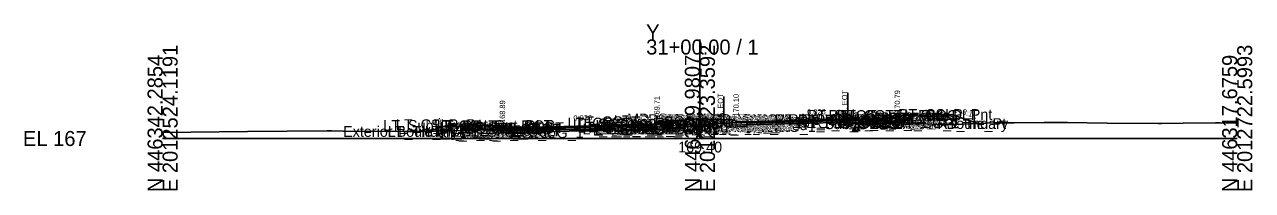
# Model space of a CAD drawing. Extents: x -26 to 3203, y -10 to 9532.
# Drawn here: x 1974.3 to 2202.8, y 4990.3 to 5021.3 of the extents above; entities that cross this region are included whole.
import ezdxf

# ---------------------------------------------------------------- set-up
doc = ezdxf.new("R2010")
doc.units = 0
for name, color, linetype in [('Default', 7, 'Continuous'), ('Exist CMT Pavement', 7, 'Continuous'), ('Exist Cross Section Cell', 7, 'Continuous'), ('Exist XS Center Line Elevation Label', 7, 'Continuous'), ('Exist XS Ground Line', 7, 'Continuous'), ('Prop CMT Conc Surface', 7, 'Continuous'), ('Prop CMT Concrete Structures', 7, 'Continuous'), ('Prop CMT Pvmt Course 1', 7, 'Continuous'), ('Prop CMT Pvmt Course 1 CG', 7, 'Continuous'), ('Prop CMT Pvmt Course 2', 7, 'Continuous'), ('Prop CMT Pvmt Course 3', 7, 'Continuous'), ('Prop CMT Pvmt Surface', 7, 'Continuous'), ('Prop CMT Pvmt Wedge Surface 2', 7, 'Continuous'), ('Prop CMT Pvmt Wedge Surface 3', 7, 'Continuous'), ('Prop CMT Slope Grass', 7, 'Continuous'), ('Prop CMT Subgrade Earthwork', 7, 'Continuous'), ('Prop XS Hydro Elevations', 7, 'Continuous'), ('Prop XS Label Text', 7, 'Continuous'), ('Prop XS SE Text', 7, 'Continuous'), ('Prop XS Side Slope Text', 7, 'Continuous'), ('Scratch_Level_0', 7, 'Continuous')]:
    doc.layers.add(name, color=color, linetype=linetype)

msp = doc.modelspace()

# ---------------------------------------------------------------- linework, layer by layer
at = {"layer": 'Exist CMT Pavement'}
msp.add_lwpolyline([(2104.43, 5002.86), (2104.43, 5002.86), (2105.54, 5002.89), (2106.21, 5002.91), (2107.69, 5002.97), (2108.73, 5003.02), (2109.96, 5003.05), (2111.26, 5003.09), (2112.93, 5003.13), (2113.77, 5003.16), (2115.18, 5003.2), (2115.89, 5003.22), (2116.19, 5003.23), (2118.43, 5003.29), (2118.78, 5003.3), (2119.68, 5003.33), (2121.53, 5003.38), (2123.82, 5003.42), (2125.6, 5003.46), (2126.34, 5003.48), (2126.99, 5003.49), (2127.53, 5003.51)], dxfattribs=at)
at = {"layer": 'Exist Cross Section Cell'}
for p, q in [((2100, 5000), (2100, 5018.46)), ((2000, 5000), (2100, 5000)), ((2100, 5000), (2200, 5000))]:
    msp.add_line(p, q, dxfattribs=at)
at = {"layer": 'Exist XS Ground Line'}
msp.add_lwpolyline([(2000, 5001.15), (2015.79, 5001.29), (2030.64, 5001.42), (2031.45, 5001.41), (2033.69, 5001.39), (2045.17, 5001.28), (2048.27, 5001.28), (2060.81, 5001.6), (2064.95, 5001.67), (2070.94, 5001.68), (2082.26, 5001.66), (2087.67, 5001.5), (2088.16, 5001.47), (2089.88, 5001.58), (2095.46, 5001.91), (2100.26, 5002.43), (2103.24, 5002.77), (2104.01, 5002.84), (2104.43, 5002.86), (2105.54, 5002.89), (2106.21, 5002.91), (2107.69, 5002.97), (2108.73, 5003.02), (2109.96, 5003.05), (2111.26, 5003.09), (2112.93, 5003.13), (2113.77, 5003.16), (2115.18, 5003.2), (2115.89, 5003.22), (2116.19, 5003.23), (2118.43, 5003.29), (2118.78, 5003.3), (2119.68, 5003.33), (2121.53, 5003.38), (2123.82, 5003.42), (2125.6, 5003.46), (2126.34, 5003.48), (2126.99, 5003.49), (2127.53, 5003.51), (2128.96, 5003.53), (2134.96, 5003.18), (2141.06, 5002.82), (2145.38, 5002.58), (2152.09, 5002.8), (2154.91, 5002.9), (2156.15, 5002.91), (2158.5, 5002.94), (2164.07, 5003.01), (2168.41, 5003.01), (2175.81, 5002.88), (2185.31, 5002.82), (2185.89, 5002.81), (2189.97, 5002.86), (2195.97, 5002.93), (2196.81, 5002.93), (2200, 5002.87)], dxfattribs=at)
at = {"layer": 'Prop CMT Conc Surface'}
for points in [[(2091.25, 5002.69), (2092, 5002.71), (2092, 5002.88), (2092.76, 5003.13)], [(2108.75, 5003.14), (2106.75, 5003.09), (2106.75, 5003.26), (2106, 5003.51)], [(2134.75, 5003.82), (2136.75, 5003.79)], [(2136.75, 5003.79), (2136.75, 5004.29), (2137.25, 5004.29)], [(2141.25, 5004.38), (2146.25, 5004.48)], [(2058.75, 5002.48), (2053.75, 5002.58)], [(2063.25, 5001.89), (2063.25, 5002.39), (2062.75, 5002.39)], [(2065.25, 5002.02), (2063.25, 5001.89)]]:
    msp.add_lwpolyline(points, dxfattribs=at)
at = {"layer": 'Prop CMT Concrete Structures'}
for points in [[(2091.25, 5002.69), (2092, 5002.71), (2092, 5002.88), (2092.76, 5003.13)], [(2091.25, 5002.11), (2091.25, 5002.69)], [(2092.76, 5003.13), (2092.76, 5002.15)], [(2108.75, 5003.14), (2106.75, 5003.09), (2106.75, 5003.26), (2106, 5003.51)], [(2106, 5003.51), (2106, 5002.49)], [(2108.75, 5002.56), (2108.75, 5003.14)], [(2134.75, 5003.82), (2136.75, 5003.79), (2136.75, 5004.29), (2137.25, 5004.29)], [(2137.25, 5004.29), (2137.25, 5003.3), (2134.75, 5003.23)], [(2134.75, 5003.23), (2134.75, 5003.82)], [(2146.25, 5004.48), (2141.25, 5004.38)], [(2141.25, 5004.38), (2141.25, 5004.04)], [(2141.25, 5004.04), (2146.25, 5004.14)], [(2146.25, 5004.14), (2146.25, 5004.48)], [(2053.75, 5002.24), (2053.75, 5002.58)], [(2053.75, 5002.58), (2058.75, 5002.48)], [(2058.75, 5002.14), (2053.75, 5002.24)], [(2058.75, 5002.48), (2058.75, 5002.14)], [(2065.25, 5002.02), (2063.25, 5001.89), (2063.25, 5002.39), (2062.75, 5002.39)], [(2062.75, 5002.39), (2062.75, 5001.37), (2065.25, 5001.43)], [(2065.25, 5001.43), (2065.25, 5002.02)], [(2092.76, 5002.15), (2091.25, 5002.11)], [(2106, 5002.49), (2108.75, 5002.56)]]:
    msp.add_lwpolyline(points, dxfattribs=at)
at = {"layer": 'Prop CMT Pvmt Course 1'}
for points in [[(2091.25, 5002.69), (2065.25, 5002.02)], [(2091.25, 5002.44), (2091.25, 5002.69)], [(2108.75, 5003.14), (2134.75, 5003.82)], [(2108.75, 5002.89), (2108.75, 5003.14)], [(2108.75, 5002.89), (2108.75, 5002.89)], [(2134.75, 5003.57), (2127.53, 5003.38)], [(2134.75, 5003.82), (2134.75, 5003.57)], [(2065.25, 5001.77), (2091.25, 5002.44)], [(2065.25, 5002.02), (2065.25, 5001.77)], [(2091.25, 5002.44), (2091.25, 5002.44), (2091.25, 5002.44)]]:
    msp.add_lwpolyline(points, dxfattribs=at)
at = {"layer": 'Prop CMT Pvmt Course 1 CG'}
for points in [[(2134.75, 5003.23), (2137.75, 5003.31), (2138.07, 5002.99)], [(2134.75, 5002.9), (2134.75, 5003.23)], [(2138.07, 5002.99), (2134.75, 5002.9)], [(2065.25, 5001.43), (2062.25, 5001.36), (2061.91, 5001.01)], [(2061.91, 5001.01), (2065.25, 5001.1)], [(2065.25, 5001.1), (2065.25, 5001.43)], [(2091.25, 5002.11), (2093.26, 5002.16), (2093.58, 5001.83)], [(2091.25, 5001.77), (2091.25, 5002.11)], [(2093.58, 5001.83), (2091.25, 5001.77)], [(2108.75, 5002.56), (2105.5, 5002.48), (2105.16, 5002.13)], [(2105.16, 5002.13), (2108.75, 5002.23)], [(2108.75, 5002.23), (2108.75, 5002.56)]]:
    msp.add_lwpolyline(points, dxfattribs=at)
at = {"layer": 'Prop CMT Pvmt Course 2'}
msp.add_lwpolyline([(2108.75, 5002.89), (2108.75, 5002.56), (2108.75, 5002.56)], close=True, dxfattribs=at)
for points in [[(2108.75, 5002.89), (2108.75, 5002.89)], [(2127.53, 5003.38), (2134.75, 5003.57)], [(2127.53, 5003.05), (2127.53, 5003.38)], [(2134.75, 5003.23), (2127.53, 5003.05)], [(2134.75, 5003.57), (2134.75, 5003.23)], [(2091.25, 5002.44), (2065.25, 5001.77)], [(2065.25, 5001.43), (2091.25, 5002.11)], [(2065.25, 5001.77), (2065.25, 5001.43)], [(2091.25, 5002.11), (2091.25, 5002.44)]]:
    msp.add_lwpolyline(points, dxfattribs=at)
at = {"layer": 'Prop CMT Pvmt Course 3'}
for points in [[(2127.53, 5003.05), (2134.75, 5003.23)], [(2127.53, 5002.71), (2127.53, 5003.05)], [(2134.75, 5002.9), (2127.53, 5002.71)], [(2134.75, 5003.23), (2134.75, 5002.9)], [(2091.25, 5002.11), (2065.25, 5001.43)], [(2065.25, 5001.1), (2091.25, 5001.77)], [(2065.25, 5001.43), (2065.25, 5001.1)], [(2091.25, 5001.77), (2091.25, 5002.11)], [(2108.75, 5002.56), (2108.75, 5002.56), (2108.75, 5002.23), (2108.75, 5002.23)], [(2108.75, 5002.23), (2108.75, 5002.56)]]:
    msp.add_lwpolyline(points, dxfattribs=at)
at = {"layer": 'Prop CMT Pvmt Surface'}
for points in [[(2091.25, 5002.69), (2065.25, 5002.02)], [(2108.75, 5003.14), (2134.75, 5003.82)]]:
    msp.add_lwpolyline(points, dxfattribs=at)
at = {"layer": 'Prop CMT Pvmt Wedge Surface 2'}
msp.add_lwpolyline([(2108.75, 5002.89), (2134.75, 5003.57)], dxfattribs=at)
at = {"layer": 'Prop CMT Pvmt Wedge Surface 3'}
msp.add_lwpolyline([(2108.75, 5002.56), (2134.75, 5003.23)], dxfattribs=at)
at = {"layer": 'Prop CMT Slope Grass'}
for points in [[(2092.76, 5003.13), (2099.38, 5003.64)], [(2106, 5003.51), (2099.38, 5003.64)], [(2137.25, 5004.29), (2146.75, 5004.48)], [(2146.75, 5004.48), (2151.82, 5002.79)], [(2053.25, 5002.58), (2049.45, 5001.31)], [(2062.75, 5002.39), (2053.25, 5002.58)]]:
    msp.add_lwpolyline(points, dxfattribs=at)
at = {"layer": 'Prop CMT Subgrade Earthwork'}
for points in [[(2095.06, 5003.3), (2093.58, 5001.83)], [(2103.74, 5003.55), (2105.16, 5002.13)], [(2108.75, 5002.23), (2108.74, 5003.02)], [(2127.53, 5002.71), (2127.54, 5003.51)], [(2127.53, 5002.71), (2134.75, 5002.9)], [(2134.75, 5002.9), (2138.07, 5002.99), (2139.42, 5004.33)], [(2134.75, 5002.9), (2134.75, 5002.9)], [(2065.25, 5001.1), (2061.91, 5001.01), (2060.49, 5002.43)], [(2091.25, 5001.77), (2065.25, 5001.1)], [(2065.25, 5001.1), (2065.25, 5001.1)], [(2093.58, 5001.83), (2091.25, 5001.77)], [(2091.25, 5001.77), (2091.25, 5001.77)], [(2091.25, 5001.77), (2091.25, 5001.77)], [(2105.16, 5002.13), (2108.75, 5002.23)], [(2108.75, 5002.23), (2108.75, 5002.23)], [(2108.75, 5002.23), (2108.75, 5002.23)]]:
    msp.add_lwpolyline(points, dxfattribs=at)
at = {"layer": 'Prop XS Label Text'}
for p, q in [((2104.43, 5007.86), (2104.43, 5002.86)), ((2127.53, 5008.51), (2127.53, 5003.51))]:
    msp.add_line(p, q, dxfattribs=at)

# ---------------------------------------------------------------- texts
at = {"layer": 'Default'}
msp.add_text('-', height=0.0001, dxfattribs=at).set_placement((2000, 5000))
at = {"layer": 'Exist Cross Section Cell'}
for s, p in [('Y', (2090, 5018.46)), ('31+00.00 / 1', (2090, 5015.66)), ('EL 167', (1974, 4998.6))]:
    msp.add_text(s, height=2.8, dxfattribs=at).set_placement(p)
for s, p in [('E 2012524.1191', (2002.8, 4990)), ('E 2012623.3592', (2102.8, 4990)), ('E 2012722.5993', (2202.8, 4990)), ('N 446342.2854', (2000, 4990)), ('N 446329.9807', (2100, 4990)), ('N 446317.6759', (2200, 4990))]:
    msp.add_text(s, height=2.8, rotation=90, dxfattribs=at).set_placement(p)
at = {"layer": 'Exist XS Center Line Elevation Label'}
msp.add_text('169.40', height=2, dxfattribs=at).set_placement((2095.95, 4997.4))
at = {"layer": 'Prop XS Hydro Elevations'}
for s, p in [('169.71', (2092.5, 5003.71)), ('170.10', (2107.25, 5004.09)), ('170.79', (2137.25, 5004.79)), ('168.89', (2063.75, 5002.89))]:
    msp.add_text(s, height=1, rotation=90, dxfattribs=at).set_placement(p)
at = {"layer": 'Prop XS Label Text'}
for p in [(2104.33, 5003.88), (2127.43, 5004.53)]:
    msp.add_text('E. EOT', height=1, rotation=90, dxfattribs=at).set_placement(p)
at = {"layer": 'Prop XS SE Text'}
for p in [(2119.98, 5004.43), (2076.48, 5003.31)]:
    msp.add_text('0.026', height=1, rotation=1.4823, dxfattribs=at).set_placement(p)
at = {"layer": 'Prop XS Side Slope Text'}
for rotation, p in [(341.5651, (2148.77, 5004.59)), (18.4349, (2050.36, 5002.4))]:
    msp.add_text('3:1', height=1, rotation=rotation, dxfattribs=at).set_placement(p)
at = {"layer": 'Scratch_Level_0'}
for s, p in [('RT_Sub_Trench_Out_DLT', (2119.94, 5003.33)), ('RT_CG_Top_Face', (2123.96, 5003.29)), ('RT_CG_Top_BOC', (2125.49, 5003.29)), ('RT_CSLP_Pnt', (2136.88, 5003.48)), ('LT_Sub_Trench_Out_DLT', (2041.06, 5001.43)), ('LT_CSLP_Pnt', (2043.42, 5001.58)), ('LT_CG_Top_Face', (2050.51, 5001.39)), ('LT_CG_Top_BOC', (2051.03, 5001.39)), ('LT_CG_Top_Gut', (2051.49, 5000.89)), ('LT_PV2_OEOT', (2055.42, 5000.77)), ('LT_PV1_OEOT', (2055.99, 5001.02)), ('LT_CG_Top_Face_Med', (2075.37, 5001.88)), ('LT_CG_Top_Gut_Med', (2076.35, 5001.71)), ('LT_CG_Top_BOC_Med', (2077.15, 5002.13)), ('LT_CG_Bot_BOC_Med', (2077.19, 5001.15)), ('LT_CG_Bot_IE_Med', (2077.31, 5001.11)), ('LT_Sub_IEOT_CG_1', (2078.12, 5000.77)), ('LT_Sub_OEEOP', (2080.46, 5000.77)), ('LT_PV2_OEEOP', (2080.56, 5001.44)), ('LT_PV3_OEEOP', (2080.56, 5001.11)), ('LT_Sub_IEEOP', (2081.11, 5000.77)), ('LT_PV2_IEEOP', (2081.2, 5001.44)), ('LT_CG1_Shelf_In', (2081.43, 5001.16)), ('LT_Sub_PGL', (2082.37, 5000.77)), ('LT_PV2_PGL', (2082.46, 5001.44)), ('LT_PV1_PGL', (2083.03, 5001.69)), ('LT_Sub_DLT_In', (2084, 5002.3)), ('LT_Sub_IEOP', (2084.34, 5000.83)), ('MD_Crown Point', (2086.45, 5002.64)), ('RT_CG_Top_BOC_Med', (2090.35, 5002.51)), ('RT_CG_Bot BOC In', (2091.84, 5001.49)), ('RT_CG_Top_BOC In', (2091.97, 5002.51)), ('RT_CG_Top FOC In', (2092.61, 5002.26)), ('RT_Sub_DLT_In', (2092.64, 5002.55)), ('RT_CG_Top_Gut In', (2092.64, 5002.09)), ('RT_CG1_Shelf_In', (2093.63, 5001.48)), ('RT_CG_Bot_IE_Med', (2094.77, 5001.56)), ('RT_PV_Sub_Tie_In', (2095.25, 5002.02)), ('RT_Sub_IEOT_CG_1', (2095.57, 5001.23)), ('RT_Sub_IEOP', (2095.87, 5001.13)), ('RT_PV_IEEOP_EG', (2096.89, 5002.02)), ('RT_Sub_IEEOP', (2098.56, 5001.23)), ('RT_PV2_IEEOP', (2098.66, 5001.89)), ('RT_PV3_IEEOP', (2098.66, 5001.56)), ('RT_Sub_PGL', (2099.82, 5001.23)), ('RT_PV2_PGL', (2099.92, 5001.89)), ('RT_PV3_PGL', (2099.92, 5001.56)), ('RT_PV1_PGL', (2100.48, 5002.14)), ('RT_PV_Sub_Tie_Out', (2113.88, 5002.53)), ('RT_PV_OEEOP_EG', (2116.46, 5002.53)), ('RT_Sub_OEEOP', (2118.13, 5001.75)), ('RT_PV2_OEEOP', (2118.22, 5002.42)), ('RT_PV3_OEEOP', (2118.22, 5002.08)), ('RT_Sub_OEOT_CG_1', (2120.92, 5001.9)), ('RT_CG1_Shelf_Out', (2124.25, 5002.31)), ('RT_CG_Bot_IE', (2124.62, 5002.23)), ('RT_Sub_OEOT', (2124.78, 5001.9)), ('RT_PV2_OEOT', (2124.88, 5002.57)), ('RT_PV3_OEOT', (2124.88, 5002.23)), ('RT_CG_Top_Gut', (2124.94, 5002.79)), ('RT_PV1_OEOT', (2125.44, 5002.82)), ('RT_CG_Bot_BOC', (2125.52, 5002.3)), ('RT_Sub_OEOP', (2128.14, 5001.99)), ('Exterior Boundary', (2135.96, 5001.79)), ('RT_Tie_Pt', (2144.22, 5001.79)), ('Exterior Boundary', (2033.59, 5000.31)), ('LT_Tie_Pt', (2041.89, 5000.31)), ('LT_CG1_Shelf_Out', (2048.8, 5000.36)), ('LT_CG_Bot_BOC', (2051.06, 5000.37)), ('LT_Sub_OEOT_CG_1', (2051.47, 5000.1)), ('LT_Sub_OEOP', (2052.02, 5000.01)), ('LT_CG_Bot_IE', (2055.16, 5000.43)), ('LT_Sub_OEOT', (2055.33, 5000.1)), ('LT_PV3_OEOT', (2055.42, 5000.43))]:
    msp.add_text(s, height=2, dxfattribs=at).set_placement(p)

doc.saveas('drawing.dxf')
